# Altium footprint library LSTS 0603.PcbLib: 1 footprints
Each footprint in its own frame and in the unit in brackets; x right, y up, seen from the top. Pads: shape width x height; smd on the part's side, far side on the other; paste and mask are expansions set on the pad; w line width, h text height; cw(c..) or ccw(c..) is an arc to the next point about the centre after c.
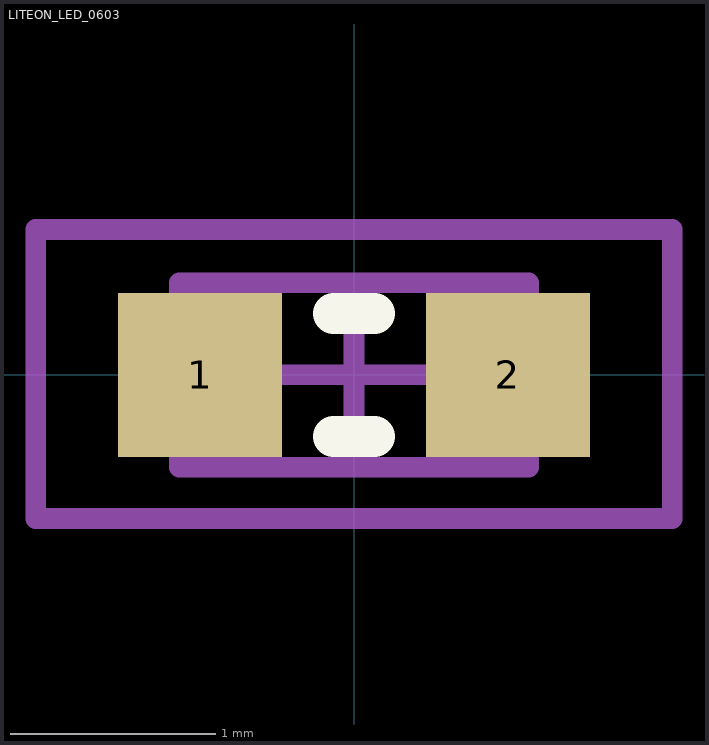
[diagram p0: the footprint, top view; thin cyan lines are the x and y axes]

## LITEON_LED_0603 [mm]
height 0.45
pads (2):
  rect 0.8x0.8 smd: 1(-0.75,0) 2(0.75,0)
Top Overlay:
  lines w0.2: -0.1,-0.3 0.1,-0.3 ; -0.1,0.3 0.1,0.3
Mechanical 13:
  lines w0.1: -0.85,-0.45 -0.85,0.45 0.85,0.45 0.85,-0.45 -0.85,-0.45
Mechanical 15:
  lines w0.05: -1.55,-0.7 -1.55,0.7 1.55,0.7 1.55,-0.7 -1.55,-0.7
  lines w0.1: -0.45,0 0.45,0 ; 0,-0.45 0,0.45
Mechanical 31:
  lines w0.102: -1.55,-0.7 1.55,-0.7 1.55,0.709 -1.55,0.709 -1.55,-0.7
  text ".Comment" at -1.3,-0.575 h0.51
  text ".Designator" at -1.3,0.075 h0.51
3D body: height 0.45, standoff 0, extent -0.55,-0.45 0.55,0.45
3D body: height 0.45, standoff 0, extent -0.85,-0.45 -0.55,0.45
3D body: height 0.45, standoff 0, extent 0.55,-0.45 0.85,0.45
